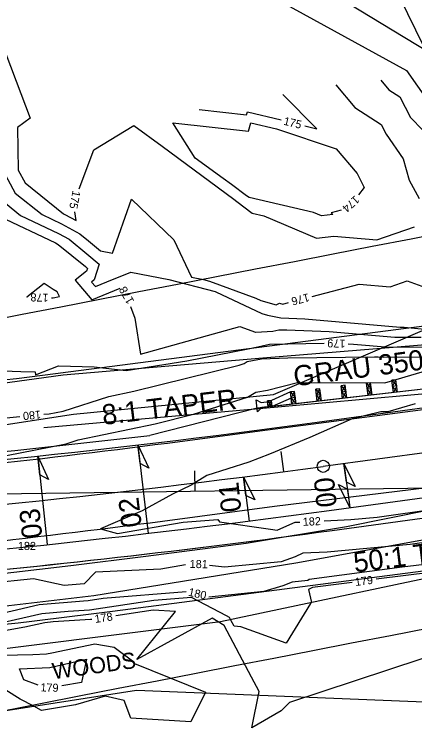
# Model space of a CAD drawing. Extents: x 2086416 to 2115205, y 575507 to 632762.
# Drawn here: x 2111355.3 to 2111454.1, y 581570.9 to 581750.1 of the extents above; entities that cross this region are included whole.
import ezdxf

# ---------------------------------------------------------------- set-up
doc = ezdxf.new("R2010")
doc.units = 0
for name, color, linetype in [('Default', 7, 'Continuous'), ('DTM Contours Major', 7, 'Continuous'), ('DTM Contours Major Text', 7, 'Continuous'), ('DTM Contours Minor', 7, 'Continuous'), ('DTM Contours Minor Text', 7, 'Continuous'), ('Exist Guardrail', 7, 'Continuous'), ('Exist Hydro Stream or Body of Water', 7, 'Continuous'), ('Exist Hydrographic FEMA Cross Section', 7, 'Continuous'), ('Exist Right of Way Line', 7, 'Continuous'), ('Exist Roads EOP', 7, 'Continuous'), ('Exist Vegetation Woods Line', 7, 'Continuous'), ('Exist Vegetation Woods Line Text', 7, 'Continuous'), ('Prop Horizontal Alignment', 7, 'Continuous'), ('Prop Horizontal Alignment Station Label', 7, 'Continuous'), ('Prop Horizontal Alignment Tick Small', 7, 'Continuous'), ('Prop SS Fill Line', 7, 'Continuous')]:
    doc.layers.add(name, color=color, linetype=linetype)

msp = doc.modelspace()

# ---------------------------------------------------------------- linework, layer by layer
at = {"layer": 'Default'}
for p, q in [((2111430.06, 581649.33), (2112312.03, 581769.69)), ((2111433.04, 581627.53), (2112315, 581747.89)), ((2111449.5, 581659.82), (2111448.51, 581659.7)), ((2111448.86, 581656.68), (2111448.51, 581659.7)), ((2111448.51, 581659.7), (2111449.68, 581658.31)), ((2111448.68, 581658.19), (2111449.5, 581659.82)), ((2111449.85, 581656.79), (2111449.5, 581659.82)), ((2111464.9, 581658.54), (2111415.22, 581652.81)), ((2111464.9, 581658.54), (2111418.46, 581653.15)), ((2111430.73, 581657.59), (2111429.74, 581657.48)), ((2111430.08, 581654.5), (2111429.74, 581657.48)), ((2111429.74, 581657.48), (2111430.9, 581656.1)), ((2111429.91, 581655.99), (2111430.73, 581657.59)), ((2111431.08, 581654.61), (2111430.73, 581657.59)), ((2111436.97, 581658.45), (2111435.98, 581658.34)), ((2111436.34, 581655.22), (2111435.98, 581658.34)), ((2111435.98, 581658.34), (2111437.15, 581656.9)), ((2111436.16, 581656.78), (2111436.97, 581658.45)), ((2111437.34, 581655.34), (2111436.97, 581658.45)), ((2111443.24, 581659.08), (2111442.25, 581658.96)), ((2111442.6, 581655.95), (2111442.25, 581658.96)), ((2111442.25, 581658.96), (2111443.42, 581657.57)), ((2111442.43, 581657.46), (2111443.24, 581659.08)), ((2111443.42, 581657.57), (2111442.43, 581657.46)), ((2111443.59, 581656.06), (2111442.43, 581657.46)), ((2111443.42, 581657.57), (2111442.6, 581655.95)), ((2111443.59, 581656.06), (2111443.24, 581659.08)), ((2111449.68, 581658.31), (2111448.68, 581658.19)), ((2111449.85, 581656.79), (2111448.68, 581658.19)), ((2111449.68, 581658.31), (2111448.86, 581656.68)), ((2111423.47, 581656.81), (2111418.78, 581654.69)), ((2111424.46, 581656.93), (2111423.47, 581656.81)), ((2111423.82, 581653.77), (2111423.47, 581656.81)), ((2111423.47, 581656.81), (2111424.64, 581655.41)), ((2111423.65, 581655.29), (2111424.46, 581656.93)), ((2111424.82, 581653.88), (2111424.46, 581656.93)), ((2111430.9, 581656.1), (2111429.91, 581655.99)), ((2111431.08, 581654.61), (2111429.91, 581655.99)), ((2111430.9, 581656.1), (2111430.08, 581654.5)), ((2111437.15, 581656.9), (2111436.16, 581656.78)), ((2111437.34, 581655.34), (2111436.16, 581656.78)), ((2111437.15, 581656.9), (2111436.34, 581655.22)), ((2111443.59, 581656.06), (2111442.6, 581655.95)), ((2111415.34, 581651.93), (2111414.95, 581654.85)), ((2111414.95, 581654.85), (2111416.23, 581654.16)), ((2111416.23, 581654.16), (2111418.26, 581654.43)), ((2111418.78, 581654.69), (2111417.79, 581654.58)), ((2111417.96, 581653.09), (2111417.79, 581654.58)), ((2111417.79, 581654.58), (2111418.96, 581653.2)), ((2111417.96, 581653.09), (2111418.78, 581654.69)), ((2111418.26, 581654.43), (2111418.34, 581653.82)), ((2111418.78, 581654.69), (2111418.29, 581654.64)), ((2111418.34, 581653.82), (2111418.42, 581653.22)), ((2111418.96, 581653.2), (2111418.78, 581654.69)), ((2111423.65, 581655.29), (2111418.96, 581653.2)), ((2111424.64, 581655.41), (2111423.65, 581655.29)), ((2111424.82, 581653.88), (2111423.65, 581655.29)), ((2111424.64, 581655.41), (2111423.82, 581653.77)), ((2111415.22, 581652.81), (2111388.72, 581646.08)), ((2111416.39, 581652.94), (2111415.34, 581651.93)), ((2111418.42, 581653.22), (2111416.39, 581652.94)), ((2111385.77, 581643.71), (2111388.33, 581621.86)), ((2111361.04, 581640.96), (2111363.36, 581619.08)), ((2111436.64, 581639.12), (2111438.13, 581628.23)), ((2111399.92, 581632.33), (2111399.85, 581637.33)), ((2111411.86, 581635.83), (2111413.26, 581624.92)), ((2110974.98, 581626.56), (2111508.23, 581633.8)), ((2111433.71, 581622.58), (2111460.81, 581626.27)), ((2111433.71, 581622.58), (2111460.81, 581626.27))]:
    msp.add_line(p, q, dxfattribs=at)
for points in [[(2111385.77, 581643.71), (2111388.45, 581637.99), (2111386.31, 581639.12)], [(2111361.04, 581640.96), (2111363.66, 581635.2), (2111361.53, 581636.36)], [(2111436.64, 581639.12), (2111439.44, 581633.45), (2111437.27, 581634.54)], [(2111411.86, 581635.83), (2111414.61, 581630.13), (2111412.45, 581631.24)], [(2111438.13, 581628.23), (2111435.34, 581633.9), (2111437.51, 581632.81)]]:
    msp.add_lwpolyline(points, close=True, dxfattribs=at)
for radius, start, end in [(2331.03, 273.81807, 277.77101), (2329.03, 273.81807, 276.75239), (2353.03, 273.81807, 277.77101), (2358.03, 275.17614, 277.77101), (2358.03, 275.17836, 277.77101)]:
    msp.add_arc((2111114.87, 583958.95), radius, start, end, dxfattribs=at)
at = {"layer": 'DTM Contours Major'}
for points in [[(2111336.48, 581784.42), (2111359.19, 581724.48), (2111356.03, 581722.18), (2111356.22, 581711.58), (2111357.93, 581708.49), (2111367.42, 581700.82), (2111367.7, 581700.69), (2111370.5, 581699.17), (2111370.16, 581701.31)], [(2111426.96, 581722.58), (2111429.99, 581721.84), (2111421.58, 581730.33)], [(2111400.94, 581726.62), (2111412.63, 581725.3), (2111412.83, 581726.02), (2111421.13, 581724)], [(2111371.28, 581707.03), (2111374.93, 581716.64), (2111384.78, 581722.6), (2111391.79, 581717.51), (2111409.44, 581704.41), (2111410.19, 581703.86), (2111414.03, 581701.01), (2111416.85, 581700.36), (2111429.92, 581694.81), (2111434.18, 581695.3), (2111444.75, 581694.38), (2111454.06, 581697.6)], [(2111362.56, 581651.3), (2111363.86, 581651.42), (2111367.3, 581652.1), (2111378.59, 581655.68), (2111384.74, 581656.96), (2111410.78, 581663.46), (2111412.04, 581663.86), (2111412.76, 581664.3), (2111416.28, 581665.01), (2111422.79, 581665.2), (2111444.21, 581665.52), (2111445.08, 581665.48), (2111446.41, 581665.36), (2111460.73, 581665.47)], [(2111261.76, 581634.8), (2111264.49, 581635.02), (2111269.8, 581635.25), (2111274.63, 581635.79), (2111286.36, 581637), (2111296.9, 581639.48), (2111308.95, 581641.32), (2111310.89, 581644.07), (2111316.03, 581645.06), (2111318.27, 581646.08), (2111327.46, 581646.18), (2111327.64, 581649.21), (2111352.5, 581650.37), (2111356.59, 581650.74)], [(2111501.47, 581623.56), (2111493.7, 581622.18), (2111485.5, 581619.95), (2111473.32, 581616.45), (2111470.82, 581616.07), (2111467.71, 581615.67), (2111457.92, 581614.37), (2111451.07, 581613.49), (2111428.1, 581610.45), (2111427.71, 581610.26), (2111423.84, 581609.83), (2111421.6, 581608.92), (2111416.91, 581607.54), (2111403.3, 581606.12)], [(2111397.68, 581607.39), (2111377.21, 581605.77), (2111373.52, 581605.22), (2111372.31, 581605.14), (2111361.36, 581604.17), (2111347.99, 581601.11), (2111339.17, 581600.17), (2111336.15, 581600.07), (2111333.7, 581599.12), (2111322.16, 581599.48), (2111304, 581596.49), (2111303.23, 581596.59), (2111302.72, 581596.56), (2111299.03, 581595.67), (2111298.77, 581595.63)]]:
    msp.add_lwpolyline(points, dxfattribs=at)
at = {"layer": 'DTM Contours Minor'}
for points in [[(2111260.91, 581756.14), (2111260.56, 581753.66), (2111263.25, 581749.57), (2111272.06, 581734.37), (2111271.17, 581754.63), (2111289.23, 581762.28), (2111298.09, 581762.28), (2111340.41, 581719.17), (2111341.02, 581718.36), (2111341.03, 581718.18), (2111350.61, 581700.9), (2111351.45, 581700.22), (2111365.39, 581693.62), (2111366.1, 581693.23), (2111372.81, 581687.77), (2111373.33, 581687.33), (2111373.12, 581686.65), (2111370.29, 581684.39), (2111374.42, 581679.53), (2111381.41, 581682.41)], [(2111434.62, 581732.71), (2111439.32, 581727.1), (2111445.84, 581722.92), (2111447.1, 581720.51), (2111451.31, 581714.39), (2111452.73, 581709.15), (2111455.2, 581704.64)], [(2111445.79, 581733.8), (2111447.75, 581731.48), (2111450.45, 581729.75), (2111453.11, 581724.62), (2111456.1, 581721.51)], [(2111394.37, 581723.34), (2111413.12, 581721.23), (2111413.68, 581723.34), (2111420, 581721.8), (2111434.73, 581716.85), (2111439.94, 581710.81), (2111441.68, 581707.35), (2111440.23, 581705.54)], [(2111435.93, 581701.69), (2111433.51, 581701.04), (2111433.92, 581700.63), (2111431.11, 581700.31), (2111429.12, 581701.15), (2111413.22, 581704.84), (2111412.61, 581705.3), (2111408.86, 581708.03), (2111406.84, 581709.53), (2111399.91, 581714.57), (2111394.37, 581723.34)], [(2111351.15, 581713.78), (2111355.49, 581705.96), (2111362.1, 581700.62), (2111366.93, 581698.33), (2111371.43, 581695.89), (2111373.55, 581694.16), (2111376.52, 581691.68), (2111379.54, 581691.09), (2111384.17, 581704.43), (2111394.67, 581694.38), (2111399.03, 581685.14), (2111401.95, 581684.57), (2111403.47, 581684.17), (2111414.91, 581679.96), (2111416.1, 581679.4), (2111419.93, 581678.31), (2111420.71, 581678.72), (2111421.55, 581678.53), (2111422.97, 581678.9)], [(2111353.05, 581703.43), (2111356.77, 581700.42), (2111366.16, 581695.97), (2111368.76, 581694.56), (2111373.18, 581690.97), (2111376.21, 581688.42), (2111374.99, 581684.48), (2111374.35, 581683.96), (2111375.28, 581682.86), (2111378.11, 581684.03), (2111383.99, 581686.43), (2111393.45, 581684.58), (2111404.87, 581681.59), (2111405, 581681.54), (2111416.4, 581676.17), (2111417.82, 581675.76), (2111421.04, 581675.1), (2111426.98, 581674.84), (2111450.57, 581672.8), (2111451.55, 581672.81), (2111457.45, 581672.2)], [(2111428.77, 581680.41), (2111440.43, 581683.45), (2111448.08, 581682.79), (2111452.29, 581684.25), (2111462.23, 581680.66)], [(2111365.87, 581681.55), (2111364.85, 581682.14), (2111362.63, 581683.58), (2111358.35, 581680.21), (2111358.43, 581680.21)], [(2111364.43, 581680.05), (2111364.85, 581680.04), (2111366.44, 581680.38), (2111365.87, 581681.55)], [(2111383.97, 581677.91), (2111385.04, 581675), (2111386.4, 581666.15), (2111410.95, 581673), (2111414.82, 581671.57), (2111414.9, 581671.59), (2111419.09, 581671.8), (2111420.57, 581672.15), (2111422.55, 581672.18), (2111433.02, 581671.72), (2111449.19, 581670.32), (2111455.74, 581670.37)], [(2111317.9, 581663.35), (2111356.87, 581661.83), (2111360.41, 581661.79), (2111360.46, 581661.01), (2111366.13, 581663.3), (2111375, 581662.98), (2111382.9, 581662.08), (2111397.84, 581664.46), (2111412.99, 581667.48), (2111414.58, 581667.75), (2111414.66, 581667.76), (2111418.31, 581668.62), (2111431.74, 581668.82)], [(2111437.73, 581668.66), (2111439.05, 581668.6), (2111447.8, 581667.84), (2111459.92, 581667.93)], [(2111269.92, 581624.06), (2111270.71, 581624.17), (2111275.89, 581625.03), (2111295.14, 581628.3), (2111310.24, 581631.56), (2111319.39, 581633.41), (2111333.07, 581637.24), (2111339.35, 581639.05), (2111342.16, 581639.08), (2111342.18, 581639.38), (2111344.6, 581639.49), (2111345.71, 581639.59), (2111368.06, 581644.02), (2111371.03, 581644.96), (2111390.01, 581648.91), (2111399.54, 581651.29), (2111412.87, 581655.54), (2111414.88, 581656.76), (2111417.77, 581657.24), (2111425.19, 581659.11), (2111446.75, 581659.06), (2111455.96, 581661.78), (2111465.02, 581661.96)], [(2111454.21, 581653.91), (2111447.47, 581651.92), (2111445.76, 581651.93), (2111438.71, 581650.16), (2111428.2, 581645.56), (2111418.25, 581641.47), (2111413.14, 581639.46), (2111402.82, 581636.18), (2111398.93, 581633.78), (2111394.3, 581631.55), (2111386.79, 581627.45), (2111376.51, 581622.98), (2111380.73, 581621.81), (2111396.95, 581624.63), (2111405.53, 581625.33), (2111405.9, 581624.74), (2111418.54, 581622.87), (2111420.17, 581622.68), (2111420.32, 581622.7), (2111420.36, 581622.71), (2111424.64, 581624.62), (2111425.77, 581624.67)], [(2111431.76, 581624.96), (2111438.32, 581625.27), (2111444.88, 581625.86), (2111459.38, 581627.95)], [(2111458.25, 581619.84), (2111453.02, 581619.09), (2111432.53, 581617.23), (2111426.48, 581616.94), (2111424.59, 581616.1), (2111421.12, 581614.85), (2111407.18, 581613.51), (2111403.49, 581613.94)], [(2111358.4, 581618.76), (2111358.22, 581618.75), (2111358.28, 581618.78), (2111359.02, 581618.95), (2111359.97, 581618.96), (2111358.47, 581618.75), (2111358.42, 581618.76), (2111358.4, 581618.76)], [(2111512.9, 581612.94), (2111502.54, 581616.24), (2111495.93, 581612.32), (2111495.05, 581609.68), (2111493.14, 581612.37), (2111486.49, 581613.5), (2111483.67, 581613.74), (2111483.2, 581613.6), (2111482.12, 581613.44), (2111472.63, 581599.99), (2111469.34, 581599.17), (2111466.84, 581596.07), (2111463.88, 581593.54), (2111423.2, 581580.1), (2111421.17, 581578.02), (2111413.92, 581573.83), (2111415.71, 581582.77), (2111413.83, 581586.35), (2111407.09, 581599.12), (2111404.08, 581600.93), (2111385.48, 581590.71), (2111395.03, 581602.54), (2111389.52, 581602.88), (2111380.32, 581601.49)], [(2111397.55, 581614.09), (2111391.47, 581612.99), (2111375.27, 581612.24), (2111372.52, 581609.42), (2111367.53, 581609.01), (2111360.01, 581610.67), (2111348.79, 581609.46)], [(2111458.61, 581612.31), (2111444.6, 581610.52)], [(2111438.65, 581609.75), (2111436.08, 581609.42), (2111428.87, 581608.47), (2111427.89, 581607.98), (2111428.68, 581604.78), (2111428.43, 581604.52), (2111422.37, 581594.71), (2111411.16, 581598.81), (2111409.52, 581598.94), (2111408.82, 581600.27), (2111408.4, 581601.08), (2111407.65, 581601.53), (2111399, 581606.02), (2111389.75, 581605.28), (2111373.81, 581602.89), (2111368.57, 581602.56), (2111362.09, 581601.98), (2111346.11, 581598.33)], [(2111374.39, 581600.6), (2111374.1, 581600.56), (2111364.82, 581599.97), (2111362.81, 581599.79), (2111357.86, 581598.66), (2111337.18, 581595.02)], [(2111348.47, 581591.69), (2111359.85, 581591.92), (2111363.21, 581592.07), (2111364.55, 581592.38), (2111375.14, 581594.6), (2111379.9, 581593.75), (2111384.79, 581590.13), (2111384.8, 581590.02), (2111384.91, 581589.73), (2111402.48, 581582.63), (2111398.82, 581575.32), (2111384.06, 581576.17), (2111382.35, 581580.57), (2111377.7, 581581.64), (2111370.4, 581579.47), (2111361.98, 581578.12), (2111360.04, 581579.14), (2111356.74, 581580.89), (2111353.12, 581583.13)], [(2111364.04, 581588.72), (2111373.11, 581590.81), (2111371.82, 581585), (2111366.95, 581584.23)], [(2111361.14, 581584.38), (2111357.61, 581585.69), (2111356.52, 581588.37), (2111364.04, 581588.72)]]:
    msp.add_lwpolyline(points, dxfattribs=at)
at = {"layer": 'Exist Guardrail'}
for points in [[(2111362.58, 581648.01), (2111389.49, 581650.44), (2111420.35, 581653.09), (2111464.12, 581657.1), (2111488.99, 581659.75), (2111513.3, 581662.17)], [(2111517.46, 581638.01), (2111492.13, 581633.89), (2111467.88, 581629.63), (2111437.3, 581623.46), (2111412.52, 581619.34), (2111387.75, 581616.15), (2111369.25, 581613.83), (2111317.74, 581607.8)]]:
    msp.add_lwpolyline(points, dxfattribs=at)
at = {"layer": 'Exist Hydro Stream or Body of Water'}
msp.add_lwpolyline([(2111463, 581737.48), (2111415.11, 581766.53), (2111397.64, 581820.96), (2111352.3, 581841.23), (2111333.83, 581869.49), (2111330, 581879.12), (2111337.82, 581902), (2111329.78, 581919.05), (2111313.88, 581938.09), (2111294.11, 581978.61), (2111295.93, 582000.43), (2111293.88, 582015.55), (2111285.78, 582045.07), (2111284.37, 582067.54), (2111288.67, 582094.58), (2111287.89, 582112.99), (2111281.07, 582150.07), (2111274.06, 582190.6)], dxfattribs=at)
at = {"layer": 'Exist Hydrographic FEMA Cross Section'}
for points in [[(2111558.92, 581715.13), (2111549.31, 581713.26), (2111539.7, 581711.4), (2111530.09, 581709.53), (2111520.48, 581707.66), (2111510.88, 581705.79), (2111501.27, 581703.93), (2111491.66, 581702.06), (2111482.06, 581700.19), (2111472.45, 581698.32), (2111462.84, 581696.46), (2111453.23, 581694.59), (2111443.62, 581692.72), (2111434.02, 581690.85), (2111424.41, 581688.98), (2111414.8, 581687.11), (2111405.19, 581685.25), (2111395.59, 581683.38), (2111385.98, 581681.51), (2111376.37, 581679.64), (2111366.77, 581677.77), (2111357.16, 581675.91), (2111347.55, 581674.04)], [(2111658.78, 581615.59), (2111477.28, 581602.23), (2111476.99, 581602.18), (2111467.38, 581600.31), (2111457.77, 581598.44), (2111448.17, 581596.57), (2111438.56, 581594.71), (2111428.95, 581592.84), (2111419.34, 581590.97), (2111409.73, 581589.1), (2111400.13, 581587.23), (2111390.52, 581585.36), (2111380.91, 581583.5), (2111371.31, 581581.63), (2111361.7, 581579.76), (2111352.09, 581577.89), (2111342.48, 581576.02), (2111332.87, 581574.15), (2111323.27, 581572.29), (2111313.66, 581570.42)]]:
    msp.add_lwpolyline(points, dxfattribs=at)
at = {"layer": 'Exist Right of Way Line'}
for points in [[(2111371.8, 581662.16), (2111512.52, 581680.42)], [(2111379.52, 581602.66), (2111520.24, 581620.92)]]:
    msp.add_lwpolyline(points, dxfattribs=at)
for radius in [1658.19, 1718.19]:
    msp.add_arc((2111158.41, 583306.56), radius, 273.81807, 277.39391, dxfattribs=at)
at = {"layer": 'Exist Roads EOP'}
for points in [[(2111417.78, 581647.42), (2111417.78, 581647.42), (2111466.25, 581653.76), (2111515.09, 581660.44), (2111516.54, 581650.63)], [(2111419.52, 581628.55), (2111419.52, 581628.55), (2111468.66, 581634.58), (2111518, 581640.73), (2111516.54, 581650.63)]]:
    msp.add_lwpolyline(points, dxfattribs=at)
for points in [[(2110977.48, 581650.48), (2111025.79, 581641.84), (2111074.55, 581635.25), (2111123.2, 581631.18), (2111172.22, 581629.18), (2111221.29, 581629.52), (2111270.17, 581631.7), (2111319.13, 581635.84), (2111368.33, 581641.12), (2111417.78, 581647.42)], [(2110973.54, 581631.44), (2111022.55, 581622.76), (2111072.45, 581615.95), (2111122.07, 581611.59), (2111171.98, 581610.01), (2111221.99, 581610.11), (2111271.48, 581612.54), (2111320.96, 581616.67), (2111370.32, 581622.18), (2111419.52, 581628.55)]]:
    msp.add_spline(points, degree=3, dxfattribs=at)
at = {"layer": 'Exist Vegetation Woods Line'}
for points in [[(2111262.29, 582184.02), (2111265.31, 582083.43), (2111279.98, 581987.09), (2111311.55, 581918.74), (2111324.25, 581867.33), (2111346.25, 581833.12), (2111371.51, 581803.94), (2111391.8, 581769.41), (2111452.1, 581736.22)], [(2111452.1, 581736.22), (2111479.27, 581697.5), (2111499.68, 581677.78), (2111492.04, 581671.34), (2111416.64, 581665.13), (2111367.28, 581660.93), (2111318.17, 581654.2), (2111268.32, 581650.61), (2111220.66, 581649.45), (2111173.29, 581649.12), (2111125.98, 581651.57), (2111078.27, 581655.72), (2111059.79, 581657.65)], [(2111257.87, 581581.4), (2111333.1, 581590.97), (2111406.18, 581600.07), (2111473.94, 581614.42), (2111501.63, 581613.42), (2111525.04, 581604.65), (2111555.79, 581590.73), (2111597.41, 581531.02), (2111635.4, 581485.12), (2111692.38, 581438.81), (2111736.92, 581397.7), (2111757.96, 581379.06)], [(2111566.76, 581548.29), (2111551.99, 581576.31), (2111385.4, 581583.05), (2111297.09, 581569.27), (2111253.55, 581562.72), (2111242.01, 581577.17), (2111257.87, 581581.4)]]:
    msp.add_lwpolyline(points, dxfattribs=at)
at = {"layer": 'Prop Horizontal Alignment'}
msp.add_line((2111431.55, 581638.43), (2112404.47, 581771.2), dxfattribs=at)
msp.add_arc((2111114.87, 583958.95), 2342.03, 273.81807, 277.77101, dxfattribs=at)
at = {"layer": 'Prop Horizontal Alignment Station Label'}
msp.add_line((2111502.04, 581648.05), (2111433.3, 581789.66), dxfattribs=at)
msp.add_circle((2111431.55, 581638.43), 1.5, dxfattribs=at)
at = {"layer": 'Prop Horizontal Alignment Tick Small'}
msp.add_line((2111421.78, 581637.12), (2111421.12, 581642.07), dxfattribs=at)
at = {"layer": 'Prop SS Fill Line'}
for p, q in [((2111419.26, 581656.2), (2111481.21, 581682.79)), ((2111369.91, 581651.29), (2111419.26, 581656.2)), ((2111320.81, 581643.91), (2111369.91, 581651.29)), ((2111424.76, 581614.57), (2111474.09, 581623.55)), ((2111374.86, 581606.53), (2111424.76, 581614.57)), ((2111324.66, 581600.66), (2111374.86, 581606.53))]:
    msp.add_line(p, q, dxfattribs=at)

# ---------------------------------------------------------------- texts
at = {"layer": 'Default'}
for s, rotation, p in [('GRAU 350 TL-3', 7.4761, (2111424.52, 581658.17)), ('8:1 TAPER', 6.8843, (2111377.21, 581648.64)), ('01', 95.9396, (2111411.35, 581627.33)), ('00', 95.9396, (2111434.93, 581628.55)), ('02', 96.7322, (2111386.75, 581623.62)), ('03', 95.9396, (2111362.2, 581620.84)), ('50:1 TAPER', 7.1182, (2111439.33, 581612.2))]:
    msp.add_text(s, height=5, rotation=rotation, dxfattribs=at).set_placement(p)
at = {"layer": 'DTM Contours Major Text'}
for s, rotation, p in [('175', 346.3238, (2111421.6, 581722.86)), ('175', 258.92, (2111369.67, 581706.65)), ('180', 185.2883, (2111361.75, 581652.23)), ('180', 347.1777, (2111398.09, 581606.49))]:
    msp.add_text(s, height=2, rotation=rotation, dxfattribs=at).set_placement(p)
at = {"layer": 'DTM Contours Minor Text'}
for s, rotation, p in [('174', 221.8811, (2111439.38, 581705.46)), ('178', 119.6875, (2111384.93, 581679.25)), ('178', 178.5046, (2111363.73, 581681.07)), ('176', 194.6174, (2111427.82, 581681.2)), ('179', 178.4055, (2111437.04, 581669.72)), ('182', 2.6959, (2111426.54, 581623.71)), ('181', 358.626, (2111398.55, 581613.34)), ('179', 7.3098, (2111439.5, 581608.85)), ('178', 8.5465, (2111375.25, 581599.72)), ('179', 358.5805, (2111361.69, 581582.82))]:
    msp.add_text(s, height=2, rotation=rotation, dxfattribs=at).set_placement(p)
msp.add_text('182', height=2, dxfattribs=at).set_placement((2111356.13, 581617.76))
at = {"layer": 'Exist Vegetation Woods Line Text'}
msp.add_text('WOODS', height=4, rotation=7.771, dxfattribs=at).set_placement((2111364.89, 581585.81))

doc.saveas('drawing.dxf')
